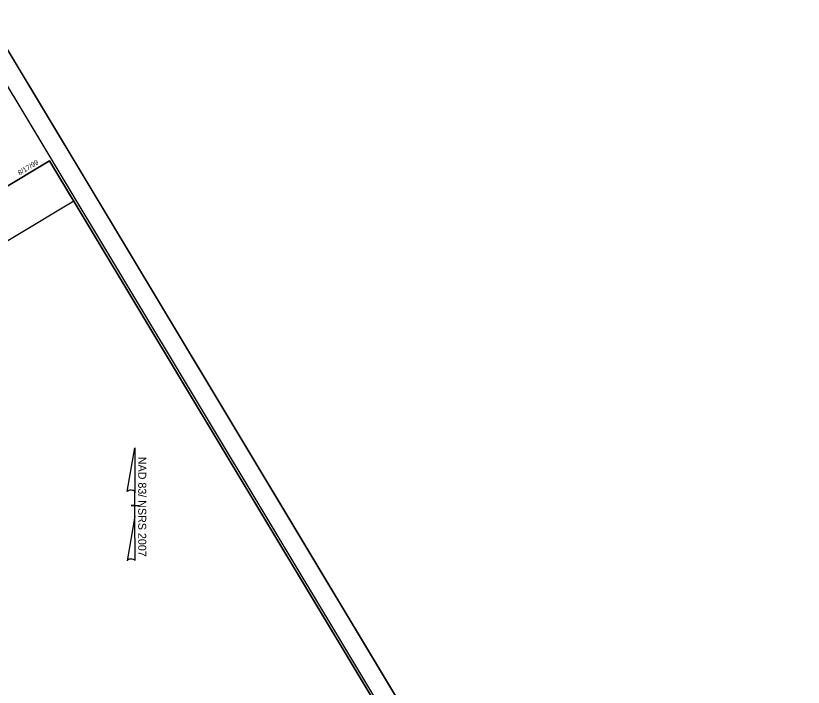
# Model space of a CAD drawing. Extents: x 1779635 to 1781473, y 814562 to 816692.
# Drawn here: x 1780604 to 1781441, y 815873 to 816587 of the extents above; entities that cross this region are included whole.
import ezdxf

# ---------------------------------------------------------------- set-up
doc = ezdxf.new("R2010")
doc.units = 0
for name, color, linetype in [('Prop North Arrow NAD83 for Plan Sheets CELL', 7, 'Continuous'), ('Sheet Clip Boundary CELL', 7, 'Continuous'), ('Sheet Cutting Line CELL', 7, 'Continuous'), ('Sheet Plan CELL', 7, 'Continuous'), ('Sheet Plan Layout CELL', 7, 'Continuous'), ('Sheet Plot Border Inside CELL', 7, 'Continuous'), ('Sheet Plot Border Outside CELL', 7, 'Continuous')]:
    doc.layers.add(name, color=color, linetype=linetype)

msp = doc.modelspace()

# ---------------------------------------------------------------- linework, layer by layer
at = {"layer": 'Prop North Arrow NAD83 for Plan Sheets CELL'}
for p, q in [((1780722.44, 816080.98), (1780730.64, 816127.33)), ((1780730.69, 816127.33), (1780730.64, 816127.33)), ((1780730.69, 816127.33), (1780730.64, 816127.33)), ((1780730.69, 816127.33), (1780730.69, 816079.53)), ((1780730.69, 816054.73), (1780730.69, 816080.93)), ((1780730.69, 816079.53), (1780730.69, 816080.88)), ((1780726.69, 816066.33), (1780726.64, 816066.33)), ((1780730.24, 816066.33), (1780726.69, 816066.33)), ((1780726.74, 816066.33), (1780734.74, 816066.33)), ((1780730.69, 816054.73), (1780722.34, 816007.48)), ((1780730.74, 816007.68), (1780730.69, 816054.73))]:
    msp.add_line(p, q, dxfattribs=at)
for centre, start_param, end_param in [((1780726.58, 816080.48), 0.216388, 2.908219), ((1780726.58, 816007.31), 0.201328, 3.141593)]:
    msp.add_ellipse(centre, major_axis=(4.23, -0.03), ratio=0.461098, start_param=start_param, end_param=end_param, dxfattribs=at)
at = {"layer": 'Sheet Clip Boundary CELL'}
msp.add_lwpolyline([(1779828.88, 815886.54), (1780515.2, 814744.31), (1781170.74, 815138.2), (1781108.01, 815242.61), (1781289.29, 815351.54), (1780665.7, 816389.35)], close=True, dxfattribs=at)
at = {"layer": 'Sheet Cutting Line CELL'}
msp.add_line((1781440.55, 815143.46), (1780573.48, 816586.5), dxfattribs=at)
at = {"layer": 'Sheet Plan CELL'}
msp.add_line((1780639.95, 816432.21), (1780639.95, 816432.21), dxfattribs=at)
for points in [[(1779739.93, 815891.42), (1780639.92, 816432.22), (1781309.49, 815317.93), (1781180.87, 815240.63), (1781283.89, 815069.16), (1780512.49, 814605.66)], [(1781412.53, 815146.43), (1780639.95, 816432.21), (1779739.93, 815891.42), (1780512.49, 814605.66)]]:
    msp.add_lwpolyline(points, close=True, dxfattribs=at)
at = {"layer": 'Sheet Plan Layout CELL'}
msp.add_lwpolyline([(1780639.92, 816432.22), (1779739.93, 815891.42), (1780512.48, 814605.67), (1781231.23, 815037.54), (1781108.01, 815242.61), (1781289.29, 815351.54)], close=True, dxfattribs=at)
at = {"layer": 'Sheet Plot Border Inside CELL'}
msp.add_lwpolyline([(1779658.72, 816021.69), (1780516.78, 814593.67), (1781421.08, 815137.02), (1780563.03, 816565.06)], close=True, dxfattribs=at)
at = {"layer": 'Sheet Plot Border Outside CELL'}
msp.add_lwpolyline([(1779634.88, 816022.53), (1780501.95, 814579.49), (1781440.55, 815143.46), (1780573.48, 816586.5)], close=True, dxfattribs=at)

# ---------------------------------------------------------------- texts
at = {"layer": 'Prop North Arrow NAD83 for Plan Sheets CELL'}
msp.add_text('NAD 83/ NSRS 2007', height=8.5, rotation=270, dxfattribs=at).set_placement((1780734.12, 816117.89))
at = {"layer": 'Sheet Plan CELL'}
msp.add_text('8/17/99', height=5.25, rotation=31, dxfattribs=at).set_placement((1780608.1, 816416.83))

doc.saveas('drawing.dxf')
